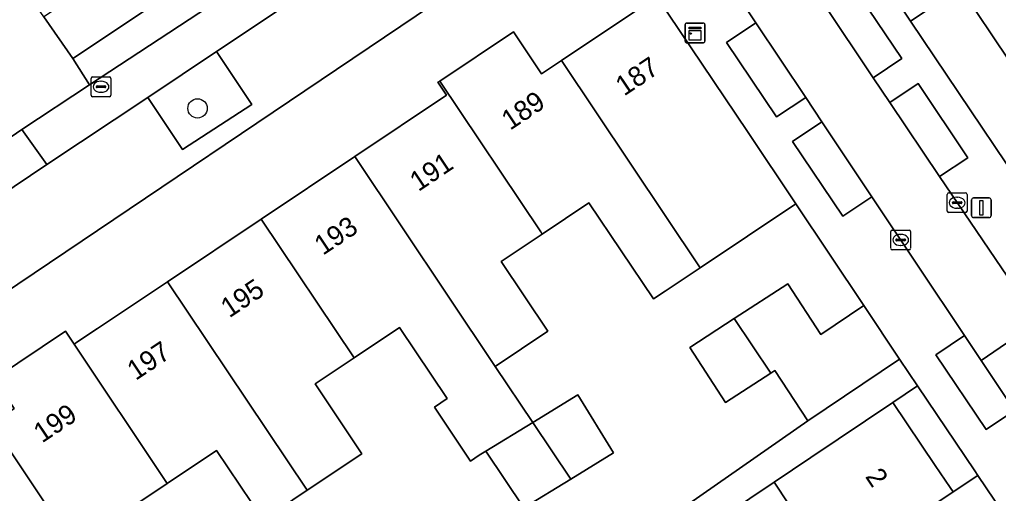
# Model space of a CAD drawing. Extents: x 158352 to 159489, y 383828 to 384603.
# Drawn here: x 158756.34 to 158805.84, y 384144.54 to 384168.53 of the extents above; entities that cross this region are included whole.
import ezdxf

# ---------------------------------------------------------------- set-up
doc = ezdxf.new("R2010")
doc.units = 0
for name, color, linetype in [('IMGEO_Boom', 7, 'Continuous'), ('IMGEO_Erf', 7, 'Continuous'), ('IMGEO_Groenvoorziening', 7, 'Continuous'), ('IMGEO_Kast', 7, 'Continuous'), ('IMGEO_Kolk', 7, 'Continuous'), ('IMGEO_Lichtmast', 7, 'Continuous'), ('IMGEO_Muur', 7, 'Continuous'), ('IMGEO_Pand', 7, 'Continuous'), ('IMGEO_Pand_nummerreeks', 7, 'Continuous'), ('IMGEO_Parkeervlak_open', 7, 'Continuous'), ('IMGEO_Rijbaan_lokaal_gesloten', 7, 'Continuous'), ('IMGEO_Rijbaan_lokaal_open', 7, 'Continuous'), ('IMGEO_Voetpad_open', 7, 'Continuous')]:
    doc.layers.add(name, color=color, linetype=linetype)

msp = doc.modelspace()

# ---------------------------------------------------------------- linework, layer by layer
at = {"layer": 'IMGEO_Boom'}
msp.add_circle((158765.335, 384164.034), 0.489, dxfattribs=at)
at = {"layer": 'IMGEO_Erf'}
for points in [[(158773.289, 384161.59), (158777.931, 384164.695), (158777.49, 384165.354), (158777.582, 384165.415), (158781.31, 384167.91), (158782.733, 384165.783), (158783.739, 384166.456), (158788.571, 384169.689), (158787.198, 384171.886), (158785.32, 384174.656), (158777.222, 384169.281), (158754.637, 384154.044), (158747.356, 384149.809), (158750.204, 384144.913), (158754.924, 384148.07), (158756.059, 384148.83), (158755.051, 384150.336), (158758.65, 384152.744), (158759.088, 384152.089), (158759.288, 384152.223), (158760.269, 384152.879), (158763.821, 384155.256), (158768.555, 384158.422)], [(158801.751, 384149.984), (158800.502, 384149.144), (158802.647, 384145.952), (158803.398, 384144.834), (158803.548, 384144.61), (158804.799, 384145.451), (158804.649, 384145.674)]]:
    msp.add_lwpolyline(points, close=True, dxfattribs=at)
for points in [[(158806.369, 384166.478), (158803.921, 384170.134), (158801.394, 384168.443), (158809.26, 384156.733)], [(158779.428, 384136.495), (158796.192, 384148.218), (158794.535, 384150.767), (158794.324, 384150.63), (158792.037, 384149.145), (158790.227, 384151.929), (158792.477, 384153.392), (158795.187, 384155.155), (158796.857, 384152.588), (158799.028, 384154.044), (158795.589, 384159.199), (158793.147, 384157.565), (158790.756, 384155.965), (158788.992, 384154.785), (158788.389, 384154.381), (158785.129, 384159.253), (158782.763, 384157.67), (158780.686, 384156.281), (158783.052, 384152.744), (158780.395, 384150.966), (158782.292, 384148.129), (158784.574, 384149.53), (158786.378, 384146.591), (158784.211, 384145.261), (158781.84, 384143.809), (158779.923, 384146.675), (158779.584, 384146.467), (158779.142, 384146.171), (158777.313, 384148.904), (158777.963, 384149.339), (158775.551, 384152.943), (158773.25, 384151.404), (158771.279, 384150.085), (158773.649, 384146.543), (158770.887, 384144.694), (158768.652, 384143.199), (158766.302, 384146.712), (158763.803, 384145.041), (158761.815, 384143.711)], [(158795.916, 384142.955), (158794.5, 384145.112), (158778.188, 384134.155)]]:
    msp.add_lwpolyline(points, dxfattribs=at)
at = {"layer": 'IMGEO_Groenvoorziening'}
msp.add_lwpolyline([(158766.3, 384166.915), (158762.82, 384164.587), (158764.575, 384161.944), (158768.085, 384164.229)], close=True, dxfattribs=at)
at = {"layer": 'IMGEO_Kast'}
for p, q in [((158789.995, 384167.43), (158789.995, 384168.271)), ((158789.995, 384168.271), (158789.995, 384167.43)), ((158790.07, 384168.355), (158790.911, 384168.355)), ((158790.911, 384168.355), (158790.07, 384168.355)), ((158790.995, 384168.28), (158790.995, 384167.439)), ((158790.995, 384167.439), (158790.995, 384168.28)), ((158790.92, 384167.355), (158790.079, 384167.355)), ((158790.079, 384167.355), (158790.92, 384167.355))]:
    msp.add_line(p, q, dxfattribs=at)
for points in [[(158790.19, 384168.145), (158790.79, 384168.145), (158790.79, 384168.06), (158790.19, 384168.06), (158790.19, 384168.145)], [(158790.19, 384167.97), (158790.79, 384167.97), (158790.79, 384167.481), (158790.19, 384167.481), (158790.19, 384167.97)]]:
    msp.add_lwpolyline(points, dxfattribs=at)
msp.add_circle((158790.274, 384167.819), 0.0377, dxfattribs=at)
for centre, start, end in [((158790.073, 384168.277), 92.4484, 184.2845), ((158790.073, 384168.277), 92.4484, 184.2845), ((158790.917, 384168.277), 2.4484, 94.2845), ((158790.917, 384168.277), 2.4484, 94.2845), ((158790.073, 384167.433), 182.4484, 274.2845), ((158790.073, 384167.433), 182.4484, 274.2845), ((158790.917, 384167.433), 272.4484, 4.2845), ((158790.917, 384167.433), 272.4484, 4.2845)]:
    msp.add_arc(centre, 0.0779, start, end, dxfattribs=at)
at = {"layer": 'IMGEO_Kolk'}
for p, q in [((158759.954, 384164.699), (158759.954, 384165.551)), ((158760.029, 384165.625), (158760.881, 384165.625)), ((158760.442, 384165.405), (158760.467, 384165.405)), ((158760.955, 384165.551), (158760.955, 384164.699)), ((158760.213, 384165.119), (158760.213, 384165.131)), ((158760.651, 384165.082), (158760.253, 384165.082)), ((158760.256, 384165.168), (158760.654, 384165.168)), ((158760.465, 384164.845), (158760.44, 384164.845)), ((158760.697, 384165.131), (158760.697, 384165.119)), ((158760.881, 384164.625), (158760.029, 384164.625)), ((158803.25, 384158.827), (158803.25, 384159.679)), ((158803.325, 384159.753), (158804.177, 384159.753)), ((158803.738, 384159.533), (158803.763, 384159.533)), ((158804.251, 384159.679), (158804.251, 384158.827)), ((158803.509, 384159.247), (158803.509, 384159.259)), ((158803.947, 384159.21), (158803.549, 384159.21)), ((158803.552, 384159.296), (158803.95, 384159.296)), ((158803.761, 384158.973), (158803.736, 384158.973)), ((158803.993, 384159.259), (158803.993, 384159.247)), ((158804.177, 384158.753), (158803.325, 384158.753)), ((158800.47, 384157.872), (158801.322, 384157.872)), ((158800.395, 384156.946), (158800.395, 384157.798)), ((158800.654, 384157.366), (158800.654, 384157.378)), ((158800.697, 384157.415), (158801.095, 384157.415)), ((158800.883, 384157.652), (158800.908, 384157.652)), ((158801.138, 384157.378), (158801.138, 384157.366)), ((158801.396, 384157.798), (158801.396, 384156.946)), ((158801.322, 384156.872), (158800.47, 384156.872)), ((158801.092, 384157.329), (158800.694, 384157.329)), ((158800.906, 384157.092), (158800.881, 384157.092))]:
    msp.add_line(p, q, dxfattribs=at)
for points in [[(158759.954, 384164.699), (158759.954, 384165.551)], [(158760.029, 384165.625), (158760.881, 384165.625)], [(158760.955, 384165.551), (158760.955, 384164.699)], [(158760.881, 384164.625), (158760.029, 384164.625)], [(158803.25, 384158.827), (158803.25, 384159.679)], [(158803.325, 384159.753), (158804.177, 384159.753)], [(158804.251, 384159.679), (158804.251, 384158.827)], [(158804.177, 384158.753), (158803.325, 384158.753)], [(158800.47, 384157.872), (158801.322, 384157.872)], [(158800.395, 384156.946), (158800.395, 384157.798)], [(158801.396, 384157.798), (158801.396, 384156.946)], [(158801.322, 384156.872), (158800.47, 384156.872)]]:
    msp.add_lwpolyline(points, dxfattribs=at)
for centre, radius, start, end in [((158760.031, 384165.549), 0.0765, 91.552, 178.448), ((158760.031, 384165.549), 0.0765, 91.552, 178.448), ((158760.879, 384165.549), 0.0765, 1.552, 88.448), ((158760.879, 384165.549), 0.0765, 1.552, 88.448), ((158760.253, 384165.128), 0.0403, 85.8775, 175.7526), ((158760.25, 384165.118), 0.0366, 178.938, 274.7102), ((158760.654, 384165.125), 0.043, 264.8664, 352.4533), ((158760.658, 384165.13), 0.0386, 1.7309, 96.639), ((158760.031, 384164.701), 0.0765, 181.552, 268.448), ((158760.031, 384164.701), 0.0765, 181.552, 268.448), ((158760.879, 384164.701), 0.0765, 271.552, 358.448), ((158760.879, 384164.701), 0.0765, 271.552, 358.448), ((158803.327, 384159.677), 0.0765, 91.552, 178.448), ((158803.327, 384159.677), 0.0765, 91.552, 178.448), ((158804.175, 384159.677), 0.0765, 1.552, 88.448), ((158804.175, 384159.677), 0.0765, 1.552, 88.448), ((158803.549, 384159.256), 0.0403, 85.8775, 175.7526), ((158803.546, 384159.246), 0.0366, 178.938, 274.7102), ((158803.95, 384159.253), 0.043, 264.8664, 352.4533), ((158803.954, 384159.258), 0.0386, 1.7309, 96.639), ((158803.327, 384158.829), 0.0765, 181.552, 268.448), ((158803.327, 384158.829), 0.0765, 181.552, 268.448), ((158804.175, 384158.829), 0.0765, 271.552, 358.448), ((158804.175, 384158.829), 0.0765, 271.552, 358.448), ((158800.472, 384157.796), 0.0765, 91.552, 178.448), ((158800.472, 384157.796), 0.0765, 91.552, 178.448), ((158801.32, 384157.796), 0.0765, 1.552, 88.448), ((158801.32, 384157.796), 0.0765, 1.552, 88.448), ((158800.694, 384157.375), 0.0403, 85.8775, 175.7526), ((158800.691, 384157.365), 0.0366, 178.938, 274.7102), ((158801.095, 384157.372), 0.043, 264.8664, 352.4533), ((158801.099, 384157.377), 0.0386, 1.7309, 96.639), ((158800.472, 384156.948), 0.0765, 181.552, 268.448), ((158800.472, 384156.948), 0.0765, 181.552, 268.448), ((158801.32, 384156.948), 0.0765, 271.552, 358.448), ((158801.32, 384156.948), 0.0765, 271.552, 358.448)]:
    msp.add_arc(centre, radius, start, end, dxfattribs=at)
for centre, major_axis, ratio, start_param, end_param in [((158760.441, 384165.125), (-0.387, 0.002), 0.722429, 4.712389, 7.853982), ((158760.466, 384165.125), (-0.39, 0.002), 0.717154, 1.570796, 4.712389), ((158803.737, 384159.253), (-0.387, 0.002), 0.722429, 4.712389, 7.853982), ((158803.762, 384159.253), (-0.39, 0.002), 0.717154, 1.570796, 4.712389), ((158800.882, 384157.372), (-0.387, 0.002), 0.722429, 4.712389, 7.853982), ((158800.907, 384157.372), (-0.39, 0.002), 0.717154, 1.570796, 4.712389)]:
    msp.add_ellipse(centre, major_axis=major_axis, ratio=ratio, start_param=start_param, end_param=end_param, dxfattribs=at)
at = {"layer": 'IMGEO_Lichtmast'}
for p, q in [((158804.477, 384158.601), (158804.477, 384159.401)), ((158804.477, 384159.401), (158804.477, 384158.601)), ((158804.577, 384159.501), (158805.367, 384159.501)), ((158805.367, 384159.501), (158804.577, 384159.501)), ((158805.467, 384159.401), (158805.467, 384158.601)), ((158805.467, 384158.601), (158805.467, 384159.401)), ((158805.367, 384158.501), (158804.577, 384158.501)), ((158804.577, 384158.501), (158805.367, 384158.501))]:
    msp.add_line(p, q, dxfattribs=at)
msp.add_lwpolyline([(158804.897, 384159.376), (158805.047, 384159.376), (158805.047, 384158.626), (158804.897, 384158.626), (158804.897, 384159.376)], dxfattribs=at)
for centre, start, end in [((158804.577, 384159.401), 90, 180), ((158804.577, 384159.401), 90, 180), ((158805.367, 384159.401), 0, 90), ((158805.367, 384159.401), 360, 90), ((158804.577, 384158.601), 180, 270), ((158804.577, 384158.601), 180, 270), ((158805.367, 384158.601), 270, 0), ((158805.367, 384158.601), 270, 0)]:
    msp.add_arc(centre, 0.1, start, end, dxfattribs=at)
at = {"layer": 'IMGEO_Muur'}
for points in [[(158801.394, 384168.443), (158809.14, 384156.911)], [(158799.028, 384154.044), (158793.143, 384162.855)]]:
    msp.add_lwpolyline(points, dxfattribs=at)
at = {"layer": 'IMGEO_Pand'}
for points in [[(158808.664, 384168.014), (158801.648, 384178.502), (158796.822, 384175.274), (158801.394, 384168.443), (158803.921, 384170.134), (158806.369, 384166.478)], [(158788.571, 384169.689), (158783.739, 384166.456), (158790.756, 384155.965), (158793.147, 384157.565), (158795.589, 384159.199), (158793.143, 384162.855)], [(158790.756, 384155.965), (158783.739, 384166.456), (158782.733, 384165.783), (158781.31, 384167.91), (158777.582, 384165.415), (158782.694, 384157.773), (158782.763, 384157.67), (158785.129, 384159.253), (158788.389, 384154.381), (158788.992, 384154.785)], [(158782.763, 384157.67), (158782.694, 384157.773), (158777.582, 384165.415), (158777.49, 384165.354), (158777.931, 384164.695), (158773.289, 384161.59), (158780.395, 384150.966), (158783.052, 384152.744), (158780.686, 384156.281)], [(158773.289, 384161.59), (158768.555, 384158.422), (158773.25, 384151.404), (158775.551, 384152.943), (158777.963, 384149.339), (158777.313, 384148.904), (158779.142, 384146.171), (158779.584, 384146.467), (158779.923, 384146.675), (158782.292, 384148.129), (158780.395, 384150.966)], [(158770.887, 384144.694), (158773.649, 384146.543), (158771.279, 384150.085), (158773.25, 384151.404), (158768.555, 384158.422), (158763.821, 384155.256)], [(158763.821, 384155.256), (158760.269, 384152.879), (158759.288, 384152.223), (158759.088, 384152.089), (158763.663, 384145.25), (158763.803, 384145.041), (158766.302, 384146.712), (158768.652, 384143.199), (158770.887, 384144.694)], [(158794.324, 384150.63), (158794.535, 384150.767), (158796.192, 384148.218), (158800.843, 384151.335), (158799.028, 384154.044), (158796.857, 384152.588), (158795.187, 384155.155), (158792.477, 384153.392)], [(158794.324, 384150.63), (158792.477, 384153.392), (158790.227, 384151.929), (158792.037, 384149.145)], [(158763.803, 384145.041), (158763.663, 384145.25), (158759.088, 384152.089), (158758.65, 384152.744), (158755.051, 384150.336), (158756.059, 384148.83), (158754.924, 384148.07), (158762.181, 384137.223), (158762.253, 384137.116), (158764.999, 384138.953), (158761.815, 384143.711)], [(158782.292, 384148.129), (158784.211, 384145.261), (158786.378, 384146.591), (158784.574, 384149.53)], [(158803.548, 384144.61), (158803.398, 384144.834), (158802.647, 384145.952), (158800.502, 384149.144), (158796.352, 384146.356), (158794.5, 384145.112), (158795.916, 384142.955), (158792.399, 384140.591), (158794.008, 384138.198)], [(158762.253, 384137.116), (158762.181, 384137.223), (158754.924, 384148.07), (158750.204, 384144.913), (158752.739, 384140.604), (158754.537, 384137.547), (158757.506, 384139.484), (158760.068, 384135.654)], [(158782.292, 384148.129), (158779.923, 384146.675), (158781.84, 384143.809), (158784.211, 384145.261)], [(158807.779, 384141.016), (158804.799, 384145.451), (158803.548, 384144.61), (158794.008, 384138.198), (158795.552, 384135.9), (158799.031, 384138.238), (158800.466, 384136.102), (158801.658, 384136.903)]]:
    msp.add_lwpolyline(points, close=True, dxfattribs=at)
at = {"layer": 'IMGEO_Parkeervlak_open'}
msp.add_lwpolyline([(158780.514, 384178.796), (158759.872, 384165.217), (158756.455, 384162.969), (158757.707, 384161.186), (158762.82, 384164.587), (158766.3, 384166.915), (158778.824, 384175.261)], dxfattribs=at)
for points in [[(158796.984, 384169.349), (158799.507, 384165.586), (158800.95, 384166.554), (158798.427, 384170.317)], [(158796.09, 384164.582), (158793.574, 384168.357), (158792.094, 384167.364), (158794.62, 384163.597)], [(158802.865, 384160.576), (158804.295, 384161.535), (158801.78, 384165.286), (158800.35, 384164.328)], [(158799.44, 384159.557), (158796.913, 384163.347), (158795.43, 384162.353), (158797.967, 384158.57)], [(158757.707, 384161.186), (158756.455, 384162.969), (158754.1, 384161.357), (158746.999, 384156.883), (158744.935, 384155.56), (158745.105, 384155.259), (158747.814, 384156.79), (158748.663, 384155.332), (158752.738, 384157.847)], [(158804.96, 384151.274), (158804.117, 384152.527), (158802.675, 384151.561), (158805.214, 384147.775), (158806.657, 384148.742)]]:
    msp.add_lwpolyline(points, close=True, dxfattribs=at)
at = {"layer": 'IMGEO_Rijbaan_lokaal_gesloten'}
msp.add_lwpolyline([(158780.514, 384178.796), (158780.635, 384178.907), (158779.647, 384180.327), (158759.023, 384166.554), (158759.872, 384165.217)], close=True, dxfattribs=at)
at = {"layer": 'IMGEO_Rijbaan_lokaal_open'}
for points in [[(158833.556, 384216.278), (158832.123, 384218.384), (158824.254, 384213.149), (158819.204, 384209.77), (158818.226, 384211.198), (158818.138, 384211.137), (158816.531, 384210.036), (158803.043, 384201.515), (158804.21, 384199.782), (158801.066, 384197.693), (158757.561, 384168.674), (158759.023, 384166.554), (158779.647, 384180.327), (158780.635, 384178.907)], [(158753.215, 384162.703), (158754.1, 384161.357), (158756.455, 384162.969), (158759.872, 384165.217), (158759.023, 384166.554), (158757.561, 384168.674), (158756.613, 384170.048), (158755.775, 384169.498)]]:
    msp.add_lwpolyline(points, dxfattribs=at)
for points in [[(158799.507, 384165.586), (158796.984, 384169.349), (158796.133, 384170.618), (158793.621, 384174.365), (158792.942, 384175.309), (158791.011, 384178.139), (158788.151, 384176.288), (158790.136, 384173.378), (158790.298, 384173.141), (158792.736, 384169.614), (158793.574, 384168.357), (158796.09, 384164.582), (158796.913, 384163.347), (158799.44, 384159.557), (158804.117, 384152.527), (158804.96, 384151.274), (158807.801, 384153.215), (158807.56, 384153.641), (158802.865, 384160.576), (158800.35, 384164.328)], [(158810.083, 384149.812), (158807.801, 384153.215), (158804.96, 384151.274), (158806.657, 384148.742), (158807.329, 384147.796), (158810.144, 384149.647)]]:
    msp.add_lwpolyline(points, close=True, dxfattribs=at)
at = {"layer": 'IMGEO_Voetpad_open'}
for points in [[(158809.26, 384156.733), (158801.394, 384168.443), (158796.822, 384175.274), (158794.611, 384178.792), (158793.73, 384180.171), (158791.011, 384178.139), (158792.942, 384175.309), (158793.621, 384174.365), (158795.052, 384175.324), (158797.564, 384171.577), (158796.133, 384170.618), (158796.984, 384169.349), (158798.427, 384170.317), (158800.95, 384166.554), (158799.507, 384165.586), (158800.35, 384164.328), (158801.78, 384165.286), (158804.295, 384161.535), (158802.865, 384160.576), (158807.56, 384153.641)], [(158746.068, 384149.06), (158747.356, 384149.809), (158754.637, 384154.044), (158777.222, 384169.281), (158785.32, 384174.656), (158788.151, 384176.288), (158787.941, 384176.601)], [(158778.824, 384175.261), (158766.3, 384166.915), (158768.085, 384164.229), (158764.575, 384161.944), (158762.82, 384164.587), (158757.707, 384161.186), (158752.738, 384157.847), (158748.663, 384155.332), (158750.151, 384152.773), (158747.404, 384151.165), (158745.988, 384153.697), (158745.105, 384155.259), (158744.935, 384155.56), (158742.681, 384154.246), (158740.575, 384153.025), (158740.457, 384152.957), (158738.971, 384152.091)], [(158788.571, 384169.689), (158793.143, 384162.855), (158795.589, 384159.199), (158799.028, 384154.044), (158800.843, 384151.335), (158801.751, 384149.984), (158804.649, 384145.674), (158804.799, 384145.451), (158807.779, 384141.016)], [(158806.657, 384148.742), (158805.214, 384147.775), (158802.675, 384151.561), (158804.117, 384152.527), (158799.44, 384159.557), (158797.967, 384158.57), (158795.43, 384162.353), (158796.913, 384163.347), (158796.09, 384164.582), (158794.62, 384163.597), (158792.094, 384167.364), (158793.574, 384168.357), (158792.736, 384169.614)]]:
    msp.add_lwpolyline(points, dxfattribs=at)
msp.add_lwpolyline([(158794.5, 384145.112), (158796.352, 384146.356), (158800.502, 384149.144), (158801.751, 384149.984), (158800.843, 384151.335), (158796.192, 384148.218), (158779.428, 384136.495), (158777.488, 384135.197), (158778.188, 384134.155)], close=True, dxfattribs=at)

# ---------------------------------------------------------------- texts
at = {"layer": 'IMGEO_Pand_nummerreeks'}
for s, rotation, p in [('187', 33.7931, (158786.909, 384164.63)), ('189', 33.7822, (158781.143, 384162.897)), ('191', 33.7822, (158776.504, 384159.795)), ('193', 33.7816, (158771.676, 384156.564)), ('195', 33.7822, (158766.942, 384153.397)), ('197', 33.7816, (158762.208, 384150.23)), ('199', 33.7816, (158757.474, 384147.063)), ('2', 303.896, (158799.073, 384145.39))]:
    msp.add_text(s, height=1, rotation=rotation, dxfattribs=at).set_placement(p)

doc.saveas('drawing.dxf')
